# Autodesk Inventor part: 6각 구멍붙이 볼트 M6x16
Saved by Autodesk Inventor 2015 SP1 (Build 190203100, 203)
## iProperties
Created: 2026-07
Part Number: 6각 구멍붙이 볼트 M6x16
Material: 일반
Document SubType Name: Modeling
Designer: user
Density: 1 g/cm^3
Appearance: 기본값
Author: user
Author: jhkim
Creation Date: 2026-07-01
Sending System: Autodesk Inventor 2027
Preprocessor: ST-DEVELOPER v20.1
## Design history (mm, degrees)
node "6각 구멍붙이 볼트 M6x161"
body "Solid1"
node "기준1"
